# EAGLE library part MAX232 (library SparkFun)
RS232 Transceiver Very common IC. This is generically called 'MAX232', but works with the 3V equivalent MAX3232 generic ICs. Field tested and mother approved. Spark Fun Electronics SKU : IC-3232-DIP and IC-3232-SMD
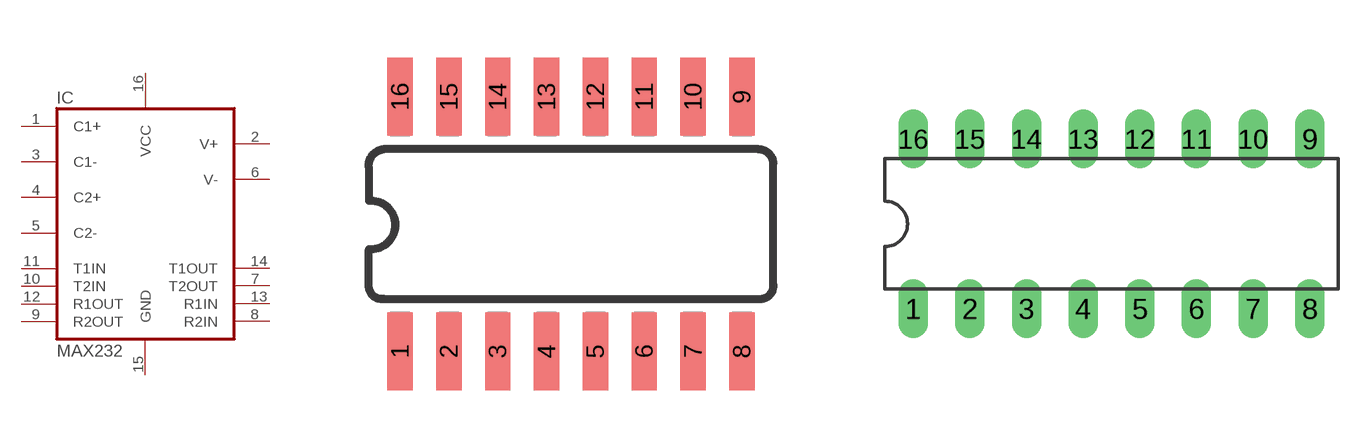
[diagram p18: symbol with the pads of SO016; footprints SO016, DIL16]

Designator prefix IC

## MAX232SOIC16  [SO016]
1  C1+
2  V+
3  C1-
4  C2+
5  C2-
6  V-
7  T2OUT  out
8  R2IN  in
9  R2OUT  out
10  T2IN  in
11  T1IN  in
12  R1OUT  out
13  R1IN  in
14  T1OUT  out
15  GND
16  VCC

## MAX232PTH  [DIL16]
Pads as for SO016

## Footprint SO016 (pad centres in mm)
smd 0.66 x 2.032: 1 -4.445,-3.315; 2 -3.175,-3.315; 3 -1.905,-3.315; 4 -0.635,-3.315; 5 0.635,-3.315; 6 1.905,-3.315; 7 3.175,-3.315; 8 4.445,-3.315; 9 4.445,3.315; 10 3.175,3.315; 11 1.905,3.315; 12 0.635,3.315; 13 -0.635,3.315; 14 -1.905,3.315; 15 -3.175,3.315; 16 -4.445,3.315

## Footprint DIL16 (pad centres in mm)
drill 0.813 long: 1 -10.16,-3.81; 2 -7.62,-3.81; 3 -5.08,-3.81; 4 -2.54,-3.81; 5 0,-3.81; 6 2.54,-3.81; 7 5.08,-3.81; 8 7.62,-3.81; 9 7.62,3.81; 10 5.08,3.81; 11 2.54,3.81; 12 0,3.81; 13 -2.54,3.81; 14 -5.08,3.81; 15 -7.62,3.81; 16 -10.16,3.81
